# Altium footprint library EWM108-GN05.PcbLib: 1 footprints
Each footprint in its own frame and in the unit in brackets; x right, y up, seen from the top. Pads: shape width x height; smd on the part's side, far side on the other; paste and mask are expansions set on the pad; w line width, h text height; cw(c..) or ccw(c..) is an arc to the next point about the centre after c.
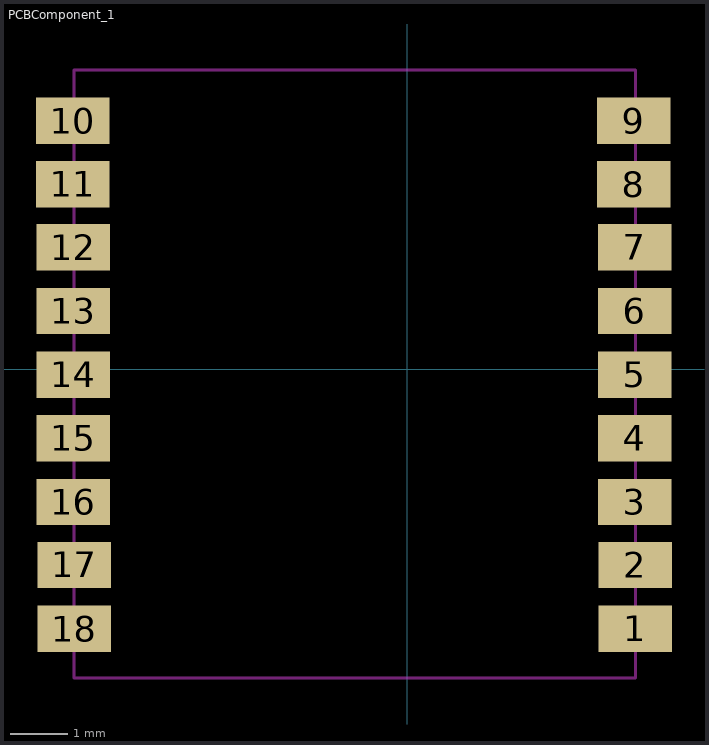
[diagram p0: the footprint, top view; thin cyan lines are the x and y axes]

## PCBComponent_1 [mm]
pads (18):
  rect 1.27x0.8 smd paste+0 mask+0: 1(3.939,-4.486) 2(3.939,-3.386) 3(3.925,-2.297) 4(3.925,-1.197) 5(3.925,-0.097) 6(3.925,1.003) 7(3.925,2.103) 8(3.911,3.192) 9(3.911,4.292) 10(-5.787,4.292) 11(-5.787,3.192) 12(-5.773,2.103) 13(-5.773,1.003) 14(-5.773,-0.097) 15(-5.773,-1.197) 16(-5.773,-2.297) 17(-5.759,-3.386) 18(-5.759,-4.486)
Keep-Out Layer:
  lines w0.05: -5.761,-5.336 3.939,-5.336 ; -5.761,-5.336 3.939,-5.336 ; -5.761,-5.336 -5.761,5.164 ; -5.761,-5.336 -5.761,5.164 ; -5.761,5.164 3.939,5.164 ; -5.761,5.164 3.939,5.164 ; 3.939,-5.336 3.939,5.164 ; 3.939,-5.336 3.939,5.164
